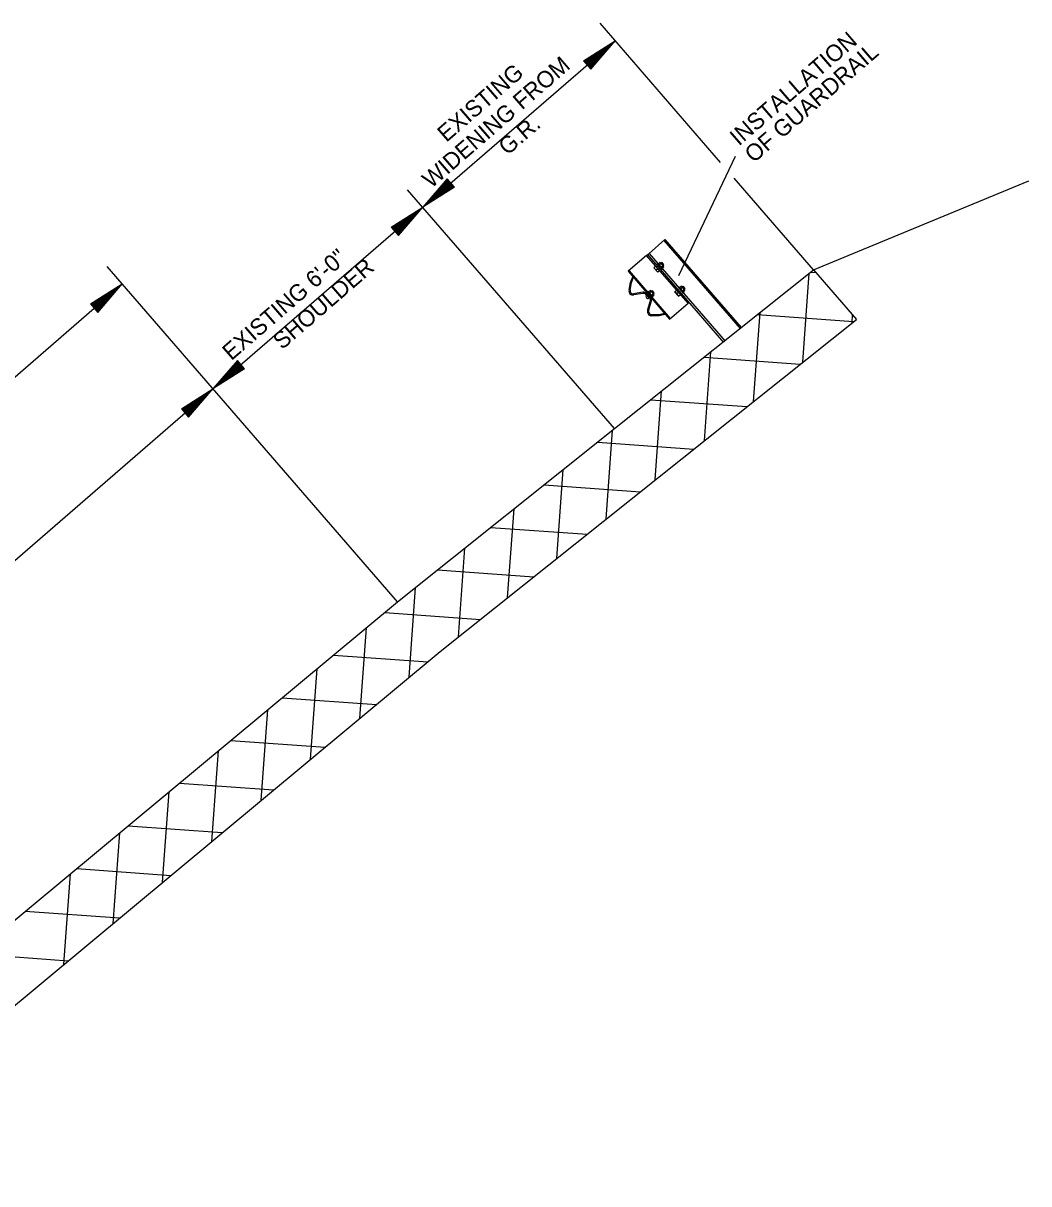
# Model space of a CAD drawing. Extents: x 192699 to 285914, y 194342 to 233219.
# Drawn here: x 262875.86 to 262897.6, y 213610.06 to 213635.15 of the extents above; entities that cross this region are included whole.
import ezdxf

# ---------------------------------------------------------------- set-up
doc = ezdxf.new("R2010")
doc.units = 0
doc.layers.add('TYPICAL SECTION FOR MOT', color=7, linetype='Continuous')

msp = doc.modelspace()

# ---------------------------------------------------------------- linework, layer by layer
at = {"layer": 'TYPICAL SECTION FOR MOT'}
for p, q in [((262890.933, 213632.143), (262888.328, 213635.153)), ((262884.497, 213631.175), (262888.655, 213634.775)), ((262887.972, 213634.342), (262888.655, 213634.775)), ((262887.985, 213634.327), (262888.554, 213634.688)), ((262888.116, 213634.176), (262888.554, 213634.688)), ((262888.129, 213634.161), (262888.655, 213634.775)), ((262887.998, 213634.312), (262888.45, 213634.598)), ((262888.011, 213634.297), (262888.349, 213634.51)), ((262888.025, 213634.281), (262888.247, 213634.422)), ((262888.076, 213634.222), (262888.247, 213634.422)), ((262888.089, 213634.206), (262888.349, 213634.51)), ((262888.102, 213634.191), (262888.45, 213634.598)), ((262887.972, 213634.342), (262888.129, 213634.161)), ((262888.038, 213634.266), (262888.146, 213634.334)), ((262888.062, 213634.237), (262888.146, 213634.334)), ((262891.25, 213632.274), (262890.021, 213629.695)), ((262885.023, 213631.79), (262884.497, 213631.175)), ((262885.036, 213631.774), (262884.598, 213631.263)), ((262885.049, 213631.759), (262884.702, 213631.353)), ((262885.154, 213631.639), (262884.702, 213631.353)), ((262885.062, 213631.744), (262884.802, 213631.44)), ((262885.141, 213631.654), (262884.802, 213631.44)), ((262885.076, 213631.728), (262884.905, 213631.529)), ((262885.127, 213631.67), (262884.905, 213631.529)), ((262885.089, 213631.713), (262885.006, 213631.616)), ((262885.114, 213631.685), (262885.006, 213631.616)), ((262885.18, 213631.608), (262885.023, 213631.79)), ((262892.943, 213629.822), (262891.226, 213631.805)), ((262892.943, 213629.822), (262897.598, 213631.745)), ((262888.641, 213626.388), (262884.169, 213631.553)), ((262885.18, 213631.608), (262884.497, 213631.175)), ((262885.167, 213631.623), (262884.598, 213631.263)), ((262879.96, 213627.248), (262884.497, 213631.175)), ((262883.813, 213630.742), (262884.497, 213631.175)), ((262883.97, 213630.561), (262884.497, 213631.175)), ((262883.826, 213630.727), (262884.396, 213631.088)), ((262883.84, 213630.712), (262884.292, 213630.998)), ((262883.853, 213630.697), (262884.191, 213630.911)), ((262883.931, 213630.607), (262884.191, 213630.911)), ((262883.944, 213630.591), (262884.292, 213630.998)), ((262883.957, 213630.576), (262884.396, 213631.088)), ((262883.813, 213630.742), (262883.97, 213630.561)), ((262883.866, 213630.681), (262884.088, 213630.822)), ((262883.88, 213630.666), (262883.987, 213630.734)), ((262883.904, 213630.637), (262883.987, 213630.734)), ((262883.917, 213630.622), (262884.088, 213630.822)), ((262889.71, 213630.455), (262891.356, 213628.554)), ((262889.732, 213630.475), (262891.378, 213628.573)), ((262889.334, 213630.133), (262889.388, 213630.176)), ((262889.334, 213630.133), (262889.339, 213630.137)), ((262891.007, 213628.252), (262889.36, 213630.155)), ((262883.947, 213622.643), (262877.67, 213629.894)), ((262889.53, 213629.895), (262889.493, 213629.863)), ((262889.585, 213629.95), (262889.622, 213629.981)), ((262889.667, 213629.855), (262889.585, 213629.95)), ((262889.605, 213629.927), (262889.642, 213629.959)), ((262889.698, 213629.903), (262889.637, 213629.974)), ((262889.647, 213629.879), (262889.684, 213629.911)), ((262889.647, 213629.879), (262889.679, 213629.907)), ((262889.667, 213629.855), (262889.705, 213629.888)), ((262888.641, 213626.388), (262892.943, 213629.822)), ((262889.852, 213628.772), (262888.962, 213629.8)), ((262888.989, 213629.549), (262889.035, 213629.667)), ((262889.01, 213629.545), (262889.047, 213629.644)), ((262889.493, 213629.863), (262889.575, 213629.769)), ((262889.535, 213629.816), (262889.578, 213629.853)), ((262889.613, 213629.802), (262889.575, 213629.769)), ((262892.713, 213627.827), (262892.851, 213629.749)), ((262892.881, 213629.772), (262892.993, 213629.764)), ((262892.943, 213629.822), (262893.87, 213628.751)), ((262866.656, 213619.698), (262877.997, 213629.516)), ((262877.313, 213629.083), (262877.997, 213629.516)), ((262877.327, 213629.068), (262877.896, 213629.429)), ((262877.457, 213628.917), (262877.896, 213629.429)), ((262877.471, 213628.902), (262877.997, 213629.516)), ((262888.959, 213629.385), (262888.989, 213629.549)), ((262888.979, 213629.381), (262889.01, 213629.545)), ((262889.375, 213629.343), (262889.411, 213629.374)), ((262889.941, 213629.346), (262889.978, 213629.378)), ((262890.044, 213629.435), (262890.081, 213629.467)), ((262890.126, 213629.341), (262890.044, 213629.435)), ((262890.064, 213629.412), (262890.102, 213629.445)), ((262890.157, 213629.388), (262890.095, 213629.46)), ((262890.106, 213629.363), (262890.144, 213629.396)), ((262890.106, 213629.363), (262890.138, 213629.392)), ((262890.126, 213629.341), (262890.163, 213629.374)), ((262877.34, 213629.053), (262877.792, 213629.339)), ((262877.353, 213629.038), (262877.691, 213629.252)), ((262877.367, 213629.022), (262877.589, 213629.163)), ((262877.418, 213628.963), (262877.589, 213629.163)), ((262877.431, 213628.948), (262877.691, 213629.252)), ((262877.444, 213628.932), (262877.792, 213629.339)), ((262889.25, 213629.336), (262889.052, 213629.303)), ((262889.254, 213629.311), (262889.056, 213629.278)), ((262889.399, 213629.199), (262889.311, 213629.297)), ((262889.417, 213629.215), (262889.33, 213629.313)), ((262889.358, 213628.964), (262889.411, 213629.138)), ((262889.457, 213629.249), (262889.375, 213629.343)), ((262889.38, 213628.956), (262889.434, 213629.131)), ((262889.395, 213629.32), (262889.432, 213629.352)), ((262889.489, 213629.296), (262889.426, 213629.368)), ((262889.437, 213629.271), (262889.474, 213629.303)), ((262889.437, 213629.271), (262889.47, 213629.299)), ((262889.457, 213629.249), (262889.495, 213629.281)), ((262890.023, 213629.252), (262889.941, 213629.346)), ((262889.983, 213629.299), (262890.025, 213629.336)), ((262890.023, 213629.252), (262890.061, 213629.284)), ((262890.23, 213629.099), (262890.256, 213629.122)), ((262877.313, 213629.083), (262877.471, 213628.902)), ((262877.38, 213629.007), (262877.488, 213629.075)), ((262877.404, 213628.978), (262877.488, 213629.075)), ((262889.725, 213628.876), (262889.607, 213628.847)), ((262891.649, 213626.978), (262891.787, 213628.9)), ((262889.607, 213628.847), (262889.441, 213628.847)), ((262889.607, 213628.826), (262889.441, 213628.826)), ((262889.568, 213625.317), (262893.87, 213628.751)), ((262889.731, 213628.857), (262889.607, 213628.826)), ((262891.728, 213628.853), (262893.81, 213628.703)), ((262893.776, 213628.676), (262893.789, 213628.845)), ((262890.576, 213627.933), (262892.657, 213627.783)), ((262890.585, 213626.129), (262890.724, 213628.051)), ((262880.487, 213627.862), (262879.96, 213627.248)), ((262880.644, 213627.681), (262879.96, 213627.248)), ((262880.5, 213627.847), (262880.061, 213627.336)), ((262880.631, 213627.696), (262880.061, 213627.336)), ((262880.513, 213627.832), (262880.165, 213627.426)), ((262880.617, 213627.712), (262880.165, 213627.426)), ((262880.526, 213627.817), (262880.266, 213627.513)), ((262880.604, 213627.727), (262880.266, 213627.513)), ((262880.54, 213627.801), (262880.369, 213627.602)), ((262880.591, 213627.742), (262880.369, 213627.602)), ((262880.553, 213627.786), (262880.47, 213627.689)), ((262880.578, 213627.758), (262880.47, 213627.689)), ((262880.644, 213627.681), (262880.487, 213627.862)), ((262868.62, 213617.43), (262879.96, 213627.248)), ((262879.277, 213626.815), (262879.96, 213627.248)), ((262879.29, 213626.8), (262879.859, 213627.161)), ((262879.421, 213626.649), (262879.859, 213627.161)), ((262879.434, 213626.634), (262879.96, 213627.248)), ((262889.522, 213625.281), (262889.66, 213627.202)), ((262879.303, 213626.785), (262879.755, 213627.071)), ((262879.317, 213626.77), (262879.655, 213626.983)), ((262879.33, 213626.754), (262879.552, 213626.895)), ((262879.381, 213626.695), (262879.552, 213626.895)), ((262879.395, 213626.679), (262879.655, 213626.983)), ((262879.408, 213626.664), (262879.755, 213627.071)), ((262889.424, 213627.013), (262891.505, 213626.864)), ((262879.277, 213626.815), (262879.434, 213626.634)), ((262879.343, 213626.739), (262879.451, 213626.807)), ((262879.368, 213626.71), (262879.451, 213626.807)), ((262883.947, 213622.643), (262888.641, 213626.388)), ((262888.458, 213624.432), (262888.596, 213626.353)), ((262888.271, 213626.094), (262890.353, 213625.944)), ((262887.394, 213623.583), (262887.533, 213625.504)), ((262884.875, 213621.572), (262889.568, 213625.317)), ((262887.119, 213625.174), (262889.2, 213625.024)), ((262886.331, 213622.734), (262886.469, 213624.655)), ((262885.967, 213624.254), (262888.048, 213624.105)), ((262885.267, 213621.885), (262885.405, 213623.806)), ((262884.814, 213623.335), (262886.896, 213623.185)), ((262884.201, 213621.012), (262884.341, 213622.957)), ((262870.103, 213611.134), (262883.947, 213622.643)), ((262883.672, 213622.414), (262885.743, 213622.265)), ((262883.135, 213620.126), (262883.276, 213622.085)), ((262871.03, 213610.063), (262884.875, 213621.572)), ((262882.563, 213621.492), (262884.602, 213621.345)), ((262882.069, 213619.239), (262882.21, 213621.198)), ((262881.453, 213620.569), (262883.492, 213620.422)), ((262881.002, 213618.353), (262881.143, 213620.312)), ((262880.343, 213619.646), (262882.382, 213619.499)), ((262879.936, 213617.466), (262880.077, 213619.425)), ((262879.233, 213618.724), (262881.272, 213618.577)), ((262878.87, 213616.58), (262879.011, 213618.539)), ((262877.803, 213615.693), (262877.944, 213617.652)), ((262878.123, 213617.801), (262880.162, 213617.654)), ((262877.013, 213616.878), (262879.052, 213616.731)), ((262876.737, 213614.807), (262876.878, 213616.766)), ((262875.903, 213615.955), (262877.942, 213615.809)), ((262874.793, 213615.033), (262876.832, 213614.886))]:
    msp.add_line(p, q, dxfattribs=at)
msp.add_lwpolyline([(262889.732, 213630.475), (262889.388, 213630.176), (262891.035, 213628.276)], dxfattribs=at)
for points in [[(262888.938, 213629.789), (262889.833, 213628.756), (262890.23, 213629.099), (262889.334, 213630.133)], [(262889.494, 213629.864), (262889.576, 213629.77), (262889.617, 213629.806), (262889.536, 213629.9)], [(262889.573, 213629.965), (262889.683, 213629.838), (262889.675, 213629.832), (262889.565, 213629.959)], [(262889.649, 213629.964), (262889.689, 213629.917), (262889.708, 213629.933), (262889.668, 213629.98)], [(262889.438, 213629.357), (262889.48, 213629.309), (262889.498, 213629.326), (262889.457, 213629.373)], [(262889.942, 213629.347), (262890.023, 213629.252), (262890.065, 213629.288), (262889.983, 213629.383)], [(262890.032, 213629.452), (262890.142, 213629.325), (262890.135, 213629.318), (262890.025, 213629.445)], [(262890.108, 213629.45), (262890.149, 213629.402), (262890.168, 213629.419), (262890.127, 213629.466)], [(262889.363, 213629.359), (262889.473, 213629.232), (262889.465, 213629.225), (262889.355, 213629.352)]]:
    msp.add_lwpolyline(points, close=True, dxfattribs=at)
for centre, radius, start, end in [((262889.62, 213629.959), 0.022, 358.6589, 86.3088), ((262889.598, 213629.878), 0.0922, 20.6256, 61.141), ((262889.68, 213629.886), 0.025, 4.2599, 79.9499), ((262889.039, 213629.363), 0.0856, 162.905, 281.6334), ((262889.039, 213629.363), 0.062, 162.905, 281.6334), ((262889.41, 213629.352), 0.022, 358.6589, 86.3088), ((262890.079, 213629.445), 0.022, 358.6589, 86.3088), ((262890.057, 213629.364), 0.0922, 20.6256, 61.141), ((262890.139, 213629.372), 0.025, 4.2599, 79.9499), ((262889.27, 213629.251), 0.0865, 45.8389, 102.7773), ((262889.27, 213629.251), 0.0622, 45.8389, 102.7773), ((262889.366, 213629.246), 0.0453, 134.8136, 297.9279), ((262889.371, 213629.162), 0.0462, 334.0297, 49.1029), ((262889.371, 213629.162), 0.0703, 334.0297, 49.1029), ((262889.388, 213629.271), 0.0922, 20.6256, 61.141), ((262889.47, 213629.279), 0.025, 4.2599, 79.9499), ((262889.462, 213628.93), 0.109, 161.7633, 255.6649), ((262889.462, 213628.93), 0.0854, 161.7633, 255.6649)]:
    msp.add_arc(centre, radius, start, end, dxfattribs=at)

# ---------------------------------------------------------------- texts
for s, p in [('INSTALLATION', (262891.329, 213632.486)), ('WIDENING FROM', (262884.679, 213631.568)), ('OF GUARDRAIL', (262891.65, 213632.118)), ('EXISTING', (262885.006, 213632.566)), ('G.R.', (262886.327, 213632.281)), ('EXISTING 6\'-0"', (262880.357, 213627.846)), ('SHOULDER', (262881.453, 213628.081))]:
    msp.add_text(s, height=0.36, rotation=40.8833, dxfattribs=at).set_placement(p)

doc.saveas('drawing.dxf')
